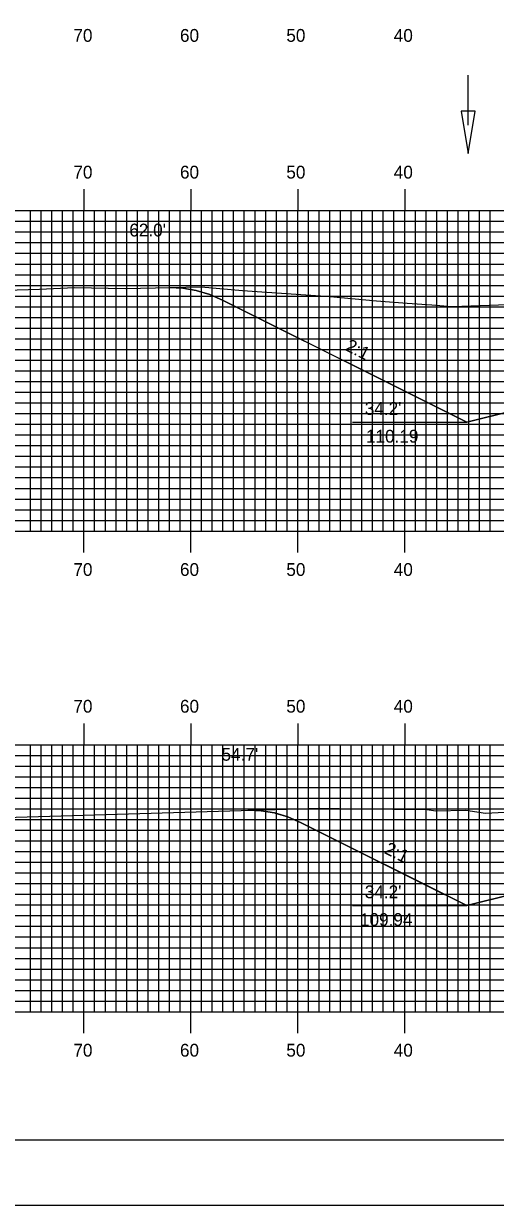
# Model space of a CAD drawing. Extents: x 1766907 to 1767250, y 442591 to 442811.
# Drawn here: x 1766996.8 to 1767040.9, y 442590.5 to 442701.2 of the extents above; entities that cross this region are included whole.
import ezdxf

# ---------------------------------------------------------------- set-up
doc = ezdxf.new("R2010")
doc.units = 0
for name, color, linetype in [('ANNOTATION', 7, 'Continuous'), ('BORDER', 7, 'Continuous'), ('D_Drainage_Ditch_Line', 7, 'Continuous'), ('D_Roadway_Centerline', 7, 'Continuous'), ('D_Roadway_SlopeLines', 7, 'Continuous'), ('D_Text_Standard', 7, 'Continuous'), ('H_V ANNOTATION', 7, 'Continuous'), ('MAJOR', 7, 'Continuous'), ('MINOR', 7, 'Continuous'), ('PDRAIN', 7, 'Continuous'), ('PLOT BOUNDARY', 7, 'Continuous'), ('S_Roadway_Centerline', 7, 'Continuous')]:
    doc.layers.add(name, color=color, linetype=linetype)

msp = doc.modelspace()

# ---------------------------------------------------------------- linework, layer by layer
at = {"layer": 'BORDER'}
msp.add_lwpolyline([(1766922.82, 442596.67), (1767242.82, 442596.67), (1767242.82, 442806.67), (1766922.82, 442806.67)], close=True, dxfattribs=at)
at = {"layer": 'D_Drainage_Ditch_Line'}
msp.add_line((1767038.36, 442691.66), (1767038.36, 442696.36), dxfattribs=at)
msp.add_lwpolyline([(1767039.02, 442692.97), (1767037.71, 442692.97), (1767038.36, 442689.03)], close=True, dxfattribs=at)
at = {"layer": 'D_Roadway_Centerline'}
for points in [[(1767010.43, 442676.47), (1767011.68, 442676.41), (1767012.93, 442676.19), (1767014.18, 442675.81), (1767015.43, 442675.26), (1767030.74, 442667.61), (1767038.25, 442663.86), (1767042.25, 442664.86), (1767052.42, 442667.4), (1767055.72, 442667.53), (1767060.42, 442667.72), (1767066.98, 442667.58), (1767072.42, 442667.46), (1767084.42, 442667.19), (1767092.42, 442666.87), (1767097.61, 442665.57), (1767102.6, 442664.33), (1767103.64, 442664.07), (1767106.6, 442663.33), (1767134.22, 442677.14)], [(1767017.74, 442627.54), (1767018.36, 442627.52), (1767018.99, 442627.49), (1767020.24, 442627.28), (1767020.29, 442627.26), (1767021.49, 442626.91), (1767022.74, 442626.36), (1767022.74, 442626.36), (1767034.22, 442620.62), (1767038.25, 442618.61), (1767038.25, 442618.61), (1767042.25, 442619.61)]]:
    msp.add_lwpolyline(points, dxfattribs=at)
at = {"layer": 'D_Roadway_SlopeLines'}
for points in [[(1767038.25, 442663.86), (1767015.43, 442675.26), (1767014.18, 442675.81), (1767012.93, 442676.19), (1767011.68, 442676.41), (1767010.43, 442676.47)], [(1767052.42, 442667.4), (1767038.25, 442663.86)], [(1767038.25, 442618.61), (1767022.74, 442626.36), (1767021.49, 442626.91), (1767020.24, 442627.28), (1767018.99, 442627.49), (1767017.74, 442627.54)], [(1767052.42, 442622.15), (1767038.25, 442618.61)]]:
    msp.add_lwpolyline(points, dxfattribs=at)
at = {"layer": 'MAJOR'}
for p, q in [((1767002.42, 442685.67), (1767002.42, 442683.67)), ((1767012.42, 442685.67), (1767012.42, 442683.67)), ((1767022.42, 442685.67), (1767022.42, 442683.67)), ((1767032.42, 442685.67), (1767032.42, 442683.67)), ((1766932.42, 442683.67), (1767212.42, 442683.67)), ((1766932.42, 442683.67), (1767212.42, 442683.67)), ((1767002.42, 442653.67), (1767002.42, 442683.67)), ((1767012.42, 442653.67), (1767012.42, 442683.67)), ((1767022.42, 442653.67), (1767022.42, 442683.67)), ((1767032.42, 442653.67), (1767032.42, 442683.67)), ((1766932.42, 442678.67), (1767212.42, 442678.67)), ((1766932.42, 442673.67), (1767212.42, 442673.67)), ((1766932.42, 442668.67), (1767212.42, 442668.67)), ((1766932.42, 442663.67), (1767212.42, 442663.67)), ((1766932.42, 442658.67), (1767212.42, 442658.67)), ((1766932.42, 442653.67), (1767212.42, 442653.67)), ((1766932.42, 442653.67), (1767212.42, 442653.67)), ((1767002.42, 442651.66), (1767002.42, 442653.67)), ((1767012.42, 442651.66), (1767012.42, 442653.67)), ((1767022.42, 442651.66), (1767022.42, 442653.67)), ((1767032.42, 442651.66), (1767032.42, 442653.67)), ((1767002.42, 442635.67), (1767002.42, 442633.67)), ((1767012.42, 442635.67), (1767012.42, 442633.67)), ((1767022.42, 442635.67), (1767022.42, 442633.67)), ((1767032.42, 442635.67), (1767032.42, 442633.67)), ((1766932.42, 442633.67), (1767212.42, 442633.67)), ((1766932.42, 442633.67), (1767212.42, 442633.67)), ((1767002.42, 442608.67), (1767002.42, 442633.67)), ((1767012.42, 442608.67), (1767012.42, 442633.67)), ((1767022.42, 442608.67), (1767022.42, 442633.67)), ((1767032.42, 442608.67), (1767032.42, 442633.67)), ((1766932.42, 442628.67), (1767212.42, 442628.67)), ((1766932.42, 442623.67), (1767212.42, 442623.67)), ((1766932.42, 442618.67), (1767212.42, 442618.67)), ((1766932.42, 442613.67), (1767212.42, 442613.67)), ((1766932.42, 442608.67), (1767212.42, 442608.67)), ((1766932.42, 442608.67), (1767212.42, 442608.67)), ((1767002.42, 442606.66), (1767002.42, 442608.67)), ((1767012.42, 442606.66), (1767012.42, 442608.67)), ((1767022.42, 442606.66), (1767022.42, 442608.67)), ((1767032.42, 442606.66), (1767032.42, 442608.67))]:
    msp.add_line(p, q, dxfattribs=at)
at = {"layer": 'MINOR'}
for p, q in [((1766997.42, 442653.67), (1766997.42, 442683.67)), ((1766998.42, 442653.67), (1766998.42, 442683.67)), ((1766999.42, 442653.67), (1766999.42, 442683.67)), ((1767000.42, 442653.67), (1767000.42, 442683.67)), ((1767001.42, 442653.67), (1767001.42, 442683.67)), ((1767003.42, 442653.67), (1767003.42, 442683.67)), ((1767004.42, 442653.67), (1767004.42, 442683.67)), ((1767005.42, 442653.67), (1767005.42, 442683.67)), ((1767006.42, 442653.67), (1767006.42, 442683.67)), ((1767007.42, 442653.67), (1767007.42, 442683.67)), ((1767008.42, 442653.67), (1767008.42, 442683.67)), ((1767009.42, 442653.67), (1767009.42, 442683.67)), ((1767010.42, 442653.67), (1767010.42, 442683.67)), ((1767011.42, 442653.67), (1767011.42, 442683.67)), ((1767013.42, 442653.67), (1767013.42, 442683.67)), ((1767014.42, 442653.67), (1767014.42, 442683.67)), ((1767015.42, 442653.67), (1767015.42, 442683.67)), ((1767016.42, 442653.67), (1767016.42, 442683.67)), ((1767017.42, 442653.67), (1767017.42, 442683.67)), ((1767018.42, 442653.67), (1767018.42, 442683.67)), ((1767019.42, 442653.67), (1767019.42, 442683.67)), ((1767020.42, 442653.67), (1767020.42, 442683.67)), ((1767021.42, 442653.67), (1767021.42, 442683.67)), ((1767023.42, 442653.67), (1767023.42, 442683.67)), ((1767024.42, 442653.67), (1767024.42, 442683.67)), ((1767025.42, 442653.67), (1767025.42, 442683.67)), ((1767026.42, 442653.67), (1767026.42, 442683.67)), ((1767027.42, 442653.67), (1767027.42, 442683.67)), ((1767028.42, 442653.67), (1767028.42, 442683.67)), ((1767029.42, 442653.67), (1767029.42, 442683.67)), ((1767030.42, 442653.67), (1767030.42, 442683.67)), ((1767031.42, 442653.67), (1767031.42, 442683.67)), ((1767033.42, 442653.67), (1767033.42, 442683.67)), ((1767034.42, 442653.67), (1767034.42, 442683.67)), ((1767035.42, 442653.67), (1767035.42, 442683.67)), ((1767036.42, 442653.67), (1767036.42, 442683.67)), ((1767037.42, 442653.67), (1767037.42, 442683.67)), ((1767038.42, 442653.67), (1767038.42, 442683.67)), ((1767039.42, 442653.67), (1767039.42, 442683.67)), ((1767040.42, 442653.67), (1767040.42, 442683.67)), ((1766932.42, 442682.67), (1767212.42, 442682.67)), ((1766932.42, 442681.67), (1767212.42, 442681.67)), ((1766932.42, 442680.67), (1767212.42, 442680.67)), ((1766932.42, 442679.67), (1767212.42, 442679.67)), ((1766932.42, 442677.67), (1767212.42, 442677.67)), ((1766932.42, 442676.67), (1767212.42, 442676.67)), ((1766932.42, 442675.67), (1767212.42, 442675.67)), ((1766932.42, 442674.67), (1767212.42, 442674.67)), ((1766932.42, 442672.67), (1767212.42, 442672.67)), ((1766932.42, 442671.67), (1767212.42, 442671.67)), ((1766932.42, 442670.67), (1767212.42, 442670.67)), ((1766932.42, 442669.67), (1767212.42, 442669.67)), ((1766932.42, 442667.67), (1767212.42, 442667.67)), ((1766932.42, 442666.67), (1767212.42, 442666.67)), ((1766932.42, 442665.67), (1767212.42, 442665.67)), ((1766932.42, 442664.67), (1767212.42, 442664.67)), ((1766932.42, 442662.67), (1767212.42, 442662.67)), ((1766932.42, 442661.67), (1767212.42, 442661.67)), ((1766932.42, 442660.67), (1767212.42, 442660.67)), ((1766932.42, 442659.67), (1767212.42, 442659.67)), ((1766932.42, 442657.67), (1767212.42, 442657.67)), ((1766932.42, 442656.67), (1767212.42, 442656.67)), ((1766932.42, 442655.67), (1767212.42, 442655.67)), ((1766932.42, 442654.67), (1767212.42, 442654.67)), ((1766997.42, 442608.67), (1766997.42, 442633.67)), ((1766998.42, 442608.67), (1766998.42, 442633.67)), ((1766999.42, 442608.67), (1766999.42, 442633.67)), ((1767000.42, 442608.67), (1767000.42, 442633.67)), ((1767001.42, 442608.67), (1767001.42, 442633.67)), ((1767003.42, 442608.67), (1767003.42, 442633.67)), ((1767004.42, 442608.67), (1767004.42, 442633.67)), ((1767005.42, 442608.67), (1767005.42, 442633.67)), ((1767006.42, 442608.67), (1767006.42, 442633.67)), ((1767007.42, 442608.67), (1767007.42, 442633.67)), ((1767008.42, 442608.67), (1767008.42, 442633.67)), ((1767009.42, 442608.67), (1767009.42, 442633.67)), ((1767010.42, 442608.67), (1767010.42, 442633.67)), ((1767011.42, 442608.67), (1767011.42, 442633.67)), ((1767013.42, 442608.67), (1767013.42, 442633.67)), ((1767014.42, 442608.67), (1767014.42, 442633.67)), ((1767015.42, 442608.67), (1767015.42, 442633.67)), ((1767016.42, 442608.67), (1767016.42, 442633.67)), ((1767017.42, 442608.67), (1767017.42, 442633.67)), ((1767018.42, 442608.67), (1767018.42, 442633.67)), ((1767019.42, 442608.67), (1767019.42, 442633.67)), ((1767020.42, 442608.67), (1767020.42, 442633.67)), ((1767021.42, 442608.67), (1767021.42, 442633.67)), ((1767023.42, 442608.67), (1767023.42, 442633.67)), ((1767024.42, 442608.67), (1767024.42, 442633.67)), ((1767025.42, 442608.67), (1767025.42, 442633.67)), ((1767026.42, 442608.67), (1767026.42, 442633.67)), ((1767027.42, 442608.67), (1767027.42, 442633.67)), ((1767028.42, 442608.67), (1767028.42, 442633.67)), ((1767029.42, 442608.67), (1767029.42, 442633.67)), ((1767030.42, 442608.67), (1767030.42, 442633.67)), ((1767031.42, 442608.67), (1767031.42, 442633.67)), ((1767033.42, 442608.67), (1767033.42, 442633.67)), ((1767034.42, 442608.67), (1767034.42, 442633.67)), ((1767035.42, 442608.67), (1767035.42, 442633.67)), ((1767036.42, 442608.67), (1767036.42, 442633.67)), ((1767037.42, 442608.67), (1767037.42, 442633.67)), ((1767038.42, 442608.67), (1767038.42, 442633.67)), ((1767039.42, 442608.67), (1767039.42, 442633.67)), ((1767040.42, 442608.67), (1767040.42, 442633.67)), ((1766932.42, 442632.67), (1767212.42, 442632.67)), ((1766932.42, 442631.67), (1767212.42, 442631.67)), ((1766932.42, 442630.67), (1767212.42, 442630.67)), ((1766932.42, 442629.67), (1767212.42, 442629.67)), ((1766932.42, 442627.67), (1767212.42, 442627.67)), ((1766932.42, 442626.67), (1767212.42, 442626.67)), ((1766932.42, 442625.67), (1767212.42, 442625.67)), ((1766932.42, 442624.67), (1767212.42, 442624.67)), ((1766932.42, 442622.67), (1767212.42, 442622.67)), ((1766932.42, 442621.67), (1767212.42, 442621.67)), ((1766932.42, 442620.67), (1767212.42, 442620.67)), ((1766932.42, 442619.67), (1767212.42, 442619.67)), ((1766932.42, 442617.67), (1767212.42, 442617.67)), ((1766932.42, 442616.67), (1767212.42, 442616.67)), ((1766932.42, 442615.67), (1767212.42, 442615.67)), ((1766932.42, 442614.67), (1767212.42, 442614.67)), ((1766932.42, 442612.67), (1767212.42, 442612.67)), ((1766932.42, 442611.67), (1767212.42, 442611.67)), ((1766932.42, 442610.67), (1767212.42, 442610.67)), ((1766932.42, 442609.67), (1767212.42, 442609.67))]:
    msp.add_line(p, q, dxfattribs=at)
at = {"layer": 'PDRAIN'}
for p, q in [((1767027.53, 442663.86), (1767038.25, 442663.86)), ((1767027.53, 442618.61), (1767038.25, 442618.61))]:
    msp.add_line(p, q, dxfattribs=at)
at = {"layer": 'PLOT BOUNDARY'}
msp.add_lwpolyline([(1766906.64, 442590.55), (1767246.64, 442590.55), (1767246.64, 442810.55), (1766906.64, 442810.55)], close=True, dxfattribs=at)
at = {"layer": 'S_Roadway_Centerline'}
for points in [[(1766988.86, 442676.02), (1766998.27, 442676.33), (1767001.53, 442676.48), (1767006.27, 442676.39), (1767013.37, 442676.52), (1767017.25, 442676.2), (1767025.44, 442675.64), (1767029.8, 442675.21), (1767032.65, 442675), (1767034.95, 442674.86), (1767036.84, 442674.69), (1767037.76, 442674.71), (1767045.46, 442675.01)], [(1766989.71, 442626.71), (1767024.47, 442627.74), (1767028.1, 442627.66), (1767034.54, 442627.6), (1767035.3, 442627.48), (1767038.13, 442627.55), (1767039.99, 442627.27), (1767044.74, 442627.52), (1767045.77, 442627.51), (1767047.42, 442627.52), (1767049.61, 442627.53), (1767061.3, 442627.65), (1767066.81, 442627.87), (1767072.68, 442627.72), (1767083.3, 442627.55), (1767084.25, 442627.5), (1767084.84, 442627.5), (1767086.38, 442627.51), (1767103.39, 442627.66), (1767115.87, 442626.68), (1767123.36, 442626.4), (1767124.52, 442626.73), (1767126.76, 442626.82), (1767129.37, 442626.65)]]:
    msp.add_lwpolyline(points, dxfattribs=at)

# ---------------------------------------------------------------- texts
at = {"layer": 'ANNOTATION'}
for rotation, p in [(333.4353, (1767026.78, 442670.63)), (333.4331, (1767030.43, 442623.55))]:
    msp.add_text('2:1', height=1.2, rotation=rotation, dxfattribs=at).set_placement(p)
for s, p in [("34.2'", (1767028.69, 442664.55)), ('110.19', (1767028.8, 442661.95)), ("34.2'", (1767028.69, 442619.3)), ('109.94', (1767028.24, 442616.7))]:
    msp.add_text(s, height=1.2, dxfattribs=at).set_placement(p)
at = {"layer": 'D_Text_Standard'}
for s, p in [("62.0'", (1767006.66, 442681.25)), ("54.7'", (1767015.29, 442632.17))]:
    msp.add_text(s, height=1.2, dxfattribs=at).set_placement(p)
at = {"layer": 'H_V ANNOTATION'}
for s, p in [('70', (1767001.43, 442699.47)), ('60', (1767011.4, 442699.47)), ('50', (1767021.35, 442699.47)), ('40', (1767031.4, 442699.47)), ('70', (1767001.43, 442686.67)), ('60', (1767011.4, 442686.67)), ('50', (1767021.35, 442686.67)), ('40', (1767031.4, 442686.67)), ('70', (1767001.43, 442649.47)), ('60', (1767011.4, 442649.47)), ('50', (1767021.35, 442649.47)), ('40', (1767031.4, 442649.47)), ('70', (1767001.43, 442636.67)), ('60', (1767011.4, 442636.67)), ('50', (1767021.35, 442636.67)), ('40', (1767031.4, 442636.67)), ('70', (1767001.43, 442604.47)), ('60', (1767011.4, 442604.47)), ('50', (1767021.35, 442604.47)), ('40', (1767031.4, 442604.47))]:
    msp.add_text(s, height=1.2, dxfattribs=at).set_placement(p)

doc.saveas('drawing.dxf')
